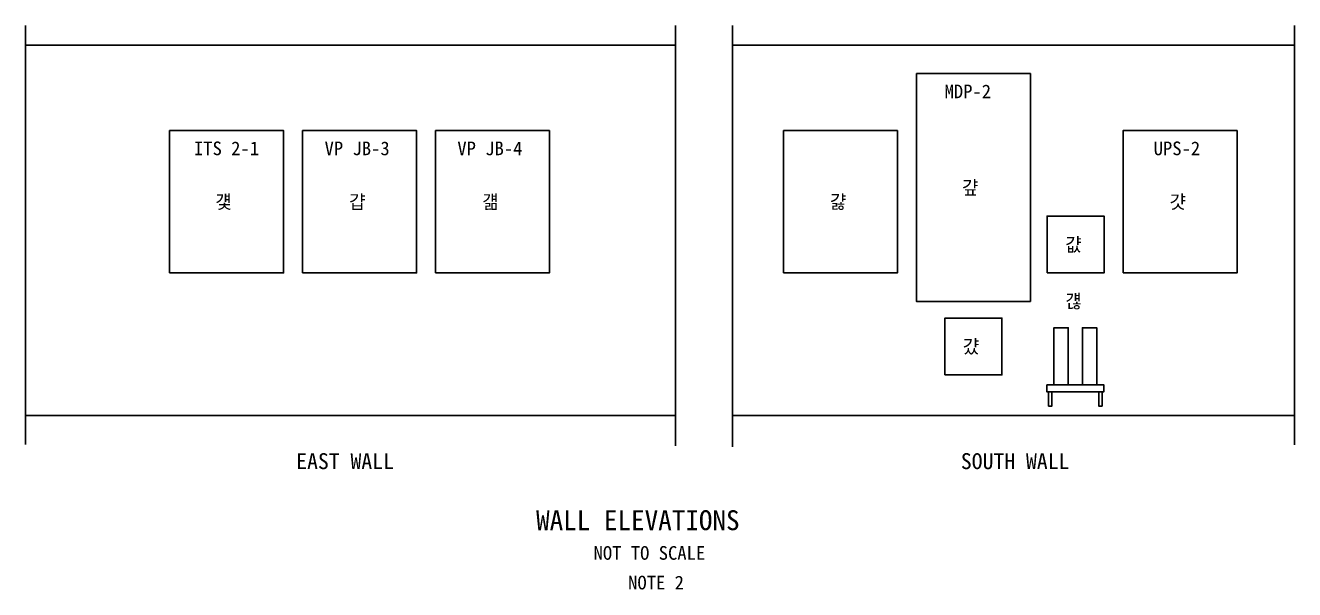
# Model space of a CAD drawing. Extents: x 0 to 22.3, y -3.1 to 6.8.
import ezdxf

# ---------------------------------------------------------------- set-up
doc = ezdxf.new("R2010")
doc.units = 0
for name, color, linetype in [('HS_Electrical_Devices', 7, 'Continuous'), ('HS_Electrical_Enclosure', 7, 'Continuous'), ('HS_Miscellaneous', 7, 'Continuous'), ('HS_Title', 7, 'Continuous'), ('Sheet_Text', 7, 'Continuous'), ('Sheets_General Details - Total Sheet Number Text', 7, 'Continuous')]:
    doc.layers.add(name, color=color, linetype=linetype)

msp = doc.modelspace()

# ---------------------------------------------------------------- linework, layer by layer
at = {"layer": 'HS_Electrical_Devices'}
for points in [[(17.929, 2.5), (18.929, 2.5), (18.929, 3.5), (17.929, 3.5)], [(16.137, 0.709), (17.137, 0.709), (17.137, 1.709), (16.137, 1.709)], [(18.3, 0.537), (18.05, 0.537), (18.05, 1.537), (18.3, 1.537)], [(18.8, 0.537), (18.55, 0.537), (18.55, 1.537), (18.8, 1.537)], [(17.925, 0.537), (18.925, 0.537), (18.925, 0.412), (17.925, 0.412)], [(18.015, 0.412), (17.955, 0.412), (17.955, 0.162), (18.015, 0.162)], [(18.895, 0.412), (18.835, 0.412), (18.835, 0.162), (18.895, 0.162)]]:
    msp.add_lwpolyline(points, close=True, dxfattribs=at)
at = {"layer": 'HS_Electrical_Enclosure'}
for points in [[(15.637, 6), (17.637, 6), (17.637, 2), (15.637, 2)], [(2.53, 2.5), (4.53, 2.5), (4.53, 5), (2.53, 5)], [(4.864, 2.5), (6.864, 2.5), (6.864, 5), (4.864, 5)], [(7.197, 2.5), (9.197, 2.5), (9.197, 5), (7.197, 5)], [(13.304, 2.5), (15.304, 2.5), (15.304, 5), (13.304, 5)], [(19.262, 2.5), (21.262, 2.5), (21.262, 5), (19.262, 5)]]:
    msp.add_lwpolyline(points, close=True, dxfattribs=at)
at = {"layer": 'HS_Miscellaneous'}
for p, q in [((11.41, 6.5), (0, 6.5)), ((22.273, 6.5), (12.41, 6.5)), ((11.41, 0), (0, 0)), ((22.273, 0), (12.41, 0))]:
    msp.add_line(p, q, dxfattribs=at)
at = {"layer": 'Sheet_Text'}
for p, q in [((0, 6.847), (0, -0.511)), ((11.41, 6.847), (11.41, -0.533)), ((12.41, 6.847), (12.41, -0.555)), ((22.273, 6.847), (22.273, -0.52))]:
    msp.add_line(p, q, dxfattribs=at)

# ---------------------------------------------------------------- texts
at = {"layer": 'HS_Title'}
for s, p in [('걒', (16.436, 3.88)), ('걉', (5.681, 3.63)), ('걞', (8.017, 3.63)), ('걇', (14.119, 3.63)), ('걋', (20.078, 3.63)), ('걊', (18.248, 2.88)), ('걚', (18.249, 1.884)), ('걌', (16.451, 1.089))]:
    msp.add_text(s, height=0.24, dxfattribs=at).set_placement(p)
at = {"layer": 'Sheets_General Details - Total Sheet Number Text'}
for s, height, p in [('MDP-2', 0.24, (16.13, 5.568)), ('ITS 2-1', 0.24, (2.958, 4.568)), ('VP JB-3', 0.24, (5.25, 4.568)), ('VP JB-4', 0.24, (7.58, 4.568)), ('UPS-2', 0.24, (19.799, 4.568)), ('걫', 0.24, (3.332, 3.63)), ('EAST WALL', 0.28, (4.753, -0.944)), ('SOUTH WALL', 0.28, (16.416, -0.944)), ('WALL ELEVATIONS', 0.35, (8.962, -2.016)), ('NOT TO SCALE ', 0.24, (9.971, -2.536)), ('NOTE 2', 0.24, (10.577, -3.056))]:
    msp.add_text(s, height=height, dxfattribs=at).set_placement(p)

doc.saveas('drawing.dxf')
